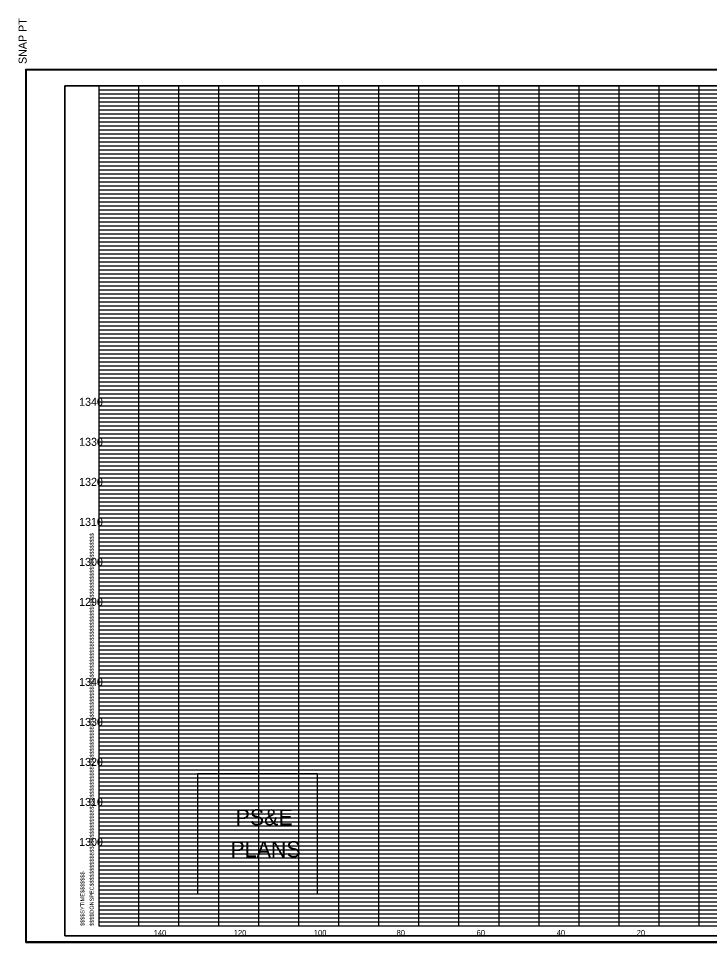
# Model space of a CAD drawing. Extents: x 980 to 1324, y 978 to 2847.
# Drawn here: x 979.9 to 1152.6, y 1805.9 to 2036.8 of the extents above; entities that cross this region are included whole.
import ezdxf

# ---------------------------------------------------------------- set-up
doc = ezdxf.new("R2010")
doc.units = 0
for name, color, linetype in [('DESIGN - SHEET - Corner Text', 7, 'Continuous'), ('DESIGN - SHEET - Light Grid', 7, 'Continuous'), ('DESIGN - SHEET - Linework', 7, 'Continuous'), ('DESIGN - SHEET - Plot Shape', 7, 'Continuous'), ('DESIGN - TYPICAL - Text', 7, 'Continuous')]:
    doc.layers.add(name, color=color, linetype=linetype)

# ---------------------------------------------------------------- blocks, each defined once
blk = doc.blocks.new('XSTSHT')
at = {"layer": 'DESIGN - SHEET - Light Grid'}
for p, q in [((0, 20.9), (8, 20.9)), ((0, 20.8), (8, 20.8)), ((8, 20.9), (16, 20.9)), ((8, 20.8), (16, 20.8)), ((0, 20.7), (8, 20.7)), ((0, 20.6), (8, 20.6)), ((8, 20.7), (16, 20.7)), ((8, 20.6), (16, 20.6)), ((0, 20.5), (8, 20.5)), ((0, 20.4), (8, 20.4)), ((8, 20.5), (16, 20.5)), ((8, 20.4), (16, 20.4)), ((0, 20.3), (8, 20.3)), ((0, 20.2), (8, 20.2)), ((0, 20.1), (8, 20.1)), ((8, 20.3), (16, 20.3)), ((8, 20.2), (16, 20.2)), ((8, 20.1), (16, 20.1)), ((0, 19.9), (8, 19.9)), ((8, 19.9), (16, 19.9)), ((0, 19.8), (8, 19.8)), ((0, 19.7), (8, 19.7)), ((8, 19.8), (16, 19.8)), ((8, 19.7), (16, 19.7)), ((0, 19.6), (8, 19.6)), ((0, 19.5), (8, 19.5)), ((0, 19.4), (8, 19.4)), ((8, 19.6), (16, 19.6)), ((8, 19.5), (16, 19.5)), ((8, 19.4), (16, 19.4)), ((0, 19.3), (8, 19.3)), ((0, 19.2), (8, 19.2)), ((8, 19.3), (16, 19.3)), ((8, 19.2), (16, 19.2)), ((0, 19.1), (8, 19.1)), ((8, 19.1), (16, 19.1)), ((0, 18.9), (8, 18.9)), ((0, 18.8), (8, 18.8)), ((8, 18.9), (16, 18.9)), ((8, 18.8), (16, 18.8)), ((0, 18.7), (8, 18.7)), ((0, 18.6), (8, 18.6)), ((0, 18.5), (8, 18.5)), ((8, 18.7), (16, 18.7)), ((8, 18.6), (16, 18.6)), ((8, 18.5), (16, 18.5)), ((0, 18.4), (8, 18.4)), ((0, 18.3), (8, 18.3)), ((8, 18.4), (16, 18.4)), ((8, 18.3), (16, 18.3)), ((0, 18.2), (8, 18.2)), ((0, 18.1), (8, 18.1)), ((8, 18.2), (16, 18.2)), ((8, 18.1), (16, 18.1)), ((0, 17.9), (8, 17.9)), ((0, 17.8), (8, 17.8)), ((8, 17.9), (16, 17.9)), ((8, 17.8), (16, 17.8)), ((0, 17.7), (8, 17.7)), ((0, 17.6), (8, 17.6)), ((8, 17.7), (16, 17.7)), ((8, 17.6), (16, 17.6)), ((0, 17.5), (8, 17.5)), ((0, 17.4), (8, 17.4)), ((8, 17.5), (16, 17.5)), ((8, 17.4), (16, 17.4)), ((0, 17.3), (8, 17.3)), ((0, 17.2), (8, 17.2)), ((0, 17.1), (8, 17.1)), ((8, 17.3), (16, 17.3)), ((8, 17.2), (16, 17.2)), ((8, 17.1), (16, 17.1)), ((0, 16.9), (8, 16.9)), ((8, 16.9), (16, 16.9)), ((0, 16.8), (8, 16.8)), ((0, 16.7), (8, 16.7)), ((8, 16.8), (16, 16.8)), ((8, 16.7), (16, 16.7)), ((0, 16.6), (8, 16.6)), ((0, 16.5), (8, 16.5)), ((0, 16.4), (8, 16.4)), ((8, 16.6), (16, 16.6)), ((8, 16.5), (16, 16.5)), ((8, 16.4), (16, 16.4)), ((0, 16.3), (8, 16.3)), ((0, 16.2), (8, 16.2)), ((8, 16.3), (16, 16.3)), ((8, 16.2), (16, 16.2)), ((0, 16.1), (8, 16.1)), ((8, 16.1), (16, 16.1)), ((0, 15.9), (8, 15.9)), ((0, 15.8), (8, 15.8)), ((8, 15.9), (16, 15.9)), ((8, 15.8), (16, 15.8)), ((0, 15.7), (8, 15.7)), ((0, 15.6), (8, 15.6)), ((0, 15.5), (8, 15.5)), ((8, 15.7), (16, 15.7)), ((8, 15.6), (16, 15.6)), ((8, 15.5), (16, 15.5)), ((0, 15.4), (8, 15.4)), ((0, 15.3), (8, 15.3)), ((8, 15.4), (16, 15.4)), ((8, 15.3), (16, 15.3)), ((0, 15.2), (8, 15.2)), ((0, 15.1), (8, 15.1)), ((8, 15.2), (16, 15.2)), ((8, 15.1), (16, 15.1)), ((0, 14.9), (8, 14.9)), ((0, 14.8), (8, 14.8)), ((8, 14.9), (16, 14.9)), ((8, 14.8), (16, 14.8)), ((0, 14.7), (8, 14.7)), ((0, 14.6), (8, 14.6)), ((8, 14.7), (16, 14.7)), ((8, 14.6), (16, 14.6)), ((0, 14.5), (8, 14.5)), ((0, 14.4), (8, 14.4)), ((8, 14.5), (16, 14.5)), ((8, 14.4), (16, 14.4)), ((0, 14.3), (8, 14.3)), ((0, 14.2), (8, 14.2)), ((0, 14.1), (8, 14.1)), ((8, 14.3), (16, 14.3)), ((8, 14.2), (16, 14.2)), ((8, 14.1), (16, 14.1)), ((0, 13.9), (8, 13.9)), ((8, 13.9), (16, 13.9)), ((0, 13.8), (8, 13.8)), ((0, 13.7), (8, 13.7)), ((8, 13.8), (16, 13.8)), ((8, 13.7), (16, 13.7)), ((0, 13.6), (8, 13.6)), ((0, 13.5), (8, 13.5)), ((0, 13.4), (8, 13.4)), ((8, 13.6), (16, 13.6)), ((8, 13.5), (16, 13.5)), ((8, 13.4), (16, 13.4)), ((0, 13.3), (8, 13.3)), ((0, 13.2), (8, 13.2)), ((8, 13.3), (16, 13.3)), ((8, 13.2), (16, 13.2)), ((0, 13.1), (8, 13.1)), ((8, 13.1), (16, 13.1)), ((0, 12.9), (8, 12.9)), ((0, 12.8), (8, 12.8)), ((8, 12.9), (16, 12.9)), ((8, 12.8), (16, 12.8)), ((0, 12.7), (8, 12.7)), ((0, 12.6), (8, 12.6)), ((0, 12.5), (8, 12.5)), ((8, 12.7), (16, 12.7)), ((8, 12.6), (16, 12.6)), ((8, 12.5), (16, 12.5)), ((0, 12.4), (8, 12.4)), ((0, 12.3), (8, 12.3)), ((8, 12.4), (16, 12.4)), ((8, 12.3), (16, 12.3)), ((0, 12.2), (8, 12.2)), ((0, 12.1), (8, 12.1)), ((8, 12.2), (16, 12.2)), ((8, 12.1), (16, 12.1)), ((0, 11.9), (8, 11.9)), ((0, 11.8), (8, 11.8)), ((8, 11.9), (16, 11.9)), ((8, 11.8), (16, 11.8)), ((0, 11.7), (8, 11.7)), ((0, 11.6), (8, 11.6)), ((8, 11.7), (16, 11.7)), ((8, 11.6), (16, 11.6)), ((0, 11.5), (8, 11.5)), ((0, 11.4), (8, 11.4)), ((8, 11.5), (16, 11.5)), ((8, 11.4), (16, 11.4)), ((0, 11.3), (8, 11.3)), ((0, 11.2), (8, 11.2)), ((0, 11.1), (8, 11.1)), ((8, 11.3), (16, 11.3)), ((8, 11.2), (16, 11.2)), ((8, 11.1), (16, 11.1)), ((0, 10.9), (8, 10.9)), ((8, 10.9), (16, 10.9)), ((0, 10.8), (8, 10.8)), ((0, 10.7), (8, 10.7)), ((8, 10.8), (16, 10.8)), ((8, 10.7), (16, 10.7)), ((0, 10.6), (8, 10.6)), ((0, 10.5), (8, 10.5)), ((0, 10.4), (8, 10.4)), ((8, 10.6), (16, 10.6)), ((8, 10.5), (16, 10.5)), ((8, 10.4), (16, 10.4)), ((0, 10.3), (8, 10.3)), ((0, 10.2), (8, 10.2)), ((8, 10.3), (16, 10.3)), ((8, 10.2), (16, 10.2)), ((0, 10.1), (8, 10.1)), ((8, 10.1), (16, 10.1)), ((0, 9.9), (8, 9.9)), ((0, 9.8), (8, 9.8)), ((0, 9.7), (8, 9.7)), ((8, 9.9), (16, 9.9)), ((8, 9.8), (16, 9.8)), ((8, 9.7), (16, 9.7)), ((0, 9.6), (8, 9.6)), ((0, 9.5), (8, 9.5)), ((8, 9.6), (16, 9.6)), ((8, 9.5), (16, 9.5)), ((0, 9.4), (8, 9.4)), ((0, 9.3), (8, 9.3)), ((8, 9.4), (16, 9.4)), ((8, 9.3), (16, 9.3)), ((0, 9.2), (8, 9.2)), ((0, 9.1), (8, 9.1)), ((8, 9.2), (16, 9.2)), ((8, 9.1), (16, 9.1)), ((0, 8.9), (8, 8.9)), ((0, 8.8), (8, 8.8)), ((8, 8.9), (16, 8.9)), ((8, 8.8), (16, 8.8)), ((0, 8.7), (8, 8.7)), ((0, 8.6), (8, 8.6)), ((8, 8.7), (16, 8.7)), ((8, 8.6), (16, 8.6)), ((0, 8.5), (8, 8.5)), ((0, 8.4), (8, 8.4)), ((8, 8.5), (16, 8.5)), ((8, 8.4), (16, 8.4)), ((0, 8.3), (8, 8.3)), ((0, 8.2), (8, 8.2)), ((0, 8.1), (8, 8.1)), ((8, 8.3), (16, 8.3)), ((8, 8.2), (16, 8.2)), ((8, 8.1), (16, 8.1)), ((0, 7.9), (8, 7.9)), ((8, 7.9), (16, 7.9)), ((0, 7.8), (8, 7.8)), ((0, 7.7), (8, 7.7)), ((8, 7.8), (16, 7.8)), ((8, 7.7), (16, 7.7)), ((0, 7.6), (8, 7.6)), ((0, 7.5), (8, 7.5)), ((0, 7.4), (8, 7.4)), ((8, 7.6), (16, 7.6)), ((8, 7.5), (16, 7.5)), ((8, 7.4), (16, 7.4)), ((0, 7.3), (8, 7.3)), ((0, 7.2), (8, 7.2)), ((8, 7.3), (16, 7.3)), ((8, 7.2), (16, 7.2)), ((0, 7.1), (8, 7.1)), ((8, 7.1), (16, 7.1)), ((0, 6.9), (8, 6.9)), ((0, 6.8), (8, 6.8)), ((0, 6.7), (8, 6.7)), ((8, 6.9), (16, 6.9)), ((8, 6.8), (16, 6.8)), ((8, 6.7), (16, 6.7)), ((0, 6.6), (8, 6.6)), ((0, 6.5), (8, 6.5)), ((8, 6.6), (16, 6.6)), ((8, 6.5), (16, 6.5)), ((0, 6.4), (8, 6.4)), ((0, 6.3), (8, 6.3)), ((8, 6.4), (16, 6.4)), ((8, 6.3), (16, 6.3)), ((0, 6.2), (8, 6.2)), ((0, 6.1), (8, 6.1)), ((8, 6.2), (16, 6.2)), ((8, 6.1), (16, 6.1)), ((0, 5.9), (8, 5.9)), ((0, 5.8), (8, 5.8)), ((8, 5.9), (16, 5.9)), ((8, 5.8), (16, 5.8)), ((0, 5.7), (8, 5.7)), ((0, 5.6), (8, 5.6)), ((8, 5.7), (16, 5.7)), ((8, 5.6), (16, 5.6)), ((0, 5.5), (8, 5.5)), ((0, 5.4), (8, 5.4)), ((8, 5.5), (16, 5.5)), ((8, 5.4), (16, 5.4)), ((0, 5.3), (8, 5.3)), ((0, 5.2), (8, 5.2)), ((0, 5.1), (8, 5.1)), ((8, 5.3), (16, 5.3)), ((8, 5.2), (16, 5.2)), ((8, 5.1), (16, 5.1)), ((0, 4.9), (8, 4.9)), ((8, 4.9), (16, 4.9)), ((0, 4.8), (8, 4.8)), ((0, 4.7), (8, 4.7)), ((8, 4.8), (16, 4.8)), ((8, 4.7), (16, 4.7)), ((0, 4.6), (8, 4.6)), ((0, 4.5), (8, 4.5)), ((0, 4.4), (8, 4.4)), ((8, 4.6), (16, 4.6)), ((8, 4.5), (16, 4.5)), ((8, 4.4), (16, 4.4)), ((0, 4.3), (8, 4.3)), ((0, 4.2), (8, 4.2)), ((8, 4.3), (16, 4.3)), ((8, 4.2), (16, 4.2)), ((0, 4.1), (8, 4.1)), ((8, 4.1), (16, 4.1)), ((0, 3.9), (8, 3.9)), ((0, 3.8), (8, 3.8)), ((0, 3.7), (8, 3.7)), ((8, 3.9), (16, 3.9)), ((8, 3.8), (16, 3.8)), ((8, 3.7), (16, 3.7)), ((0, 3.6), (8, 3.6)), ((0, 3.5), (8, 3.5)), ((8, 3.6), (16, 3.6)), ((8, 3.5), (16, 3.5)), ((0, 3.4), (8, 3.4)), ((0, 3.3), (8, 3.3)), ((8, 3.4), (16, 3.4)), ((8, 3.3), (16, 3.3)), ((0, 3.2), (8, 3.2)), ((0, 3.1), (8, 3.1)), ((8, 3.2), (16, 3.2)), ((8, 3.1), (16, 3.1)), ((0, 2.9), (8, 2.9)), ((0, 2.8), (8, 2.8)), ((8, 2.9), (16, 2.9)), ((8, 2.8), (16, 2.8)), ((0, 2.7), (8, 2.7)), ((0, 2.6), (8, 2.6)), ((8, 2.7), (16, 2.7)), ((8, 2.6), (16, 2.6)), ((0, 2.5), (8, 2.5)), ((0, 2.4), (8, 2.4)), ((8, 2.5), (16, 2.5)), ((8, 2.4), (16, 2.4)), ((0, 2.3), (8, 2.3)), ((0, 2.2), (8, 2.2)), ((0, 2.1), (8, 2.1)), ((8, 2.3), (16, 2.3)), ((8, 2.2), (16, 2.2)), ((8, 2.1), (16, 2.1)), ((0, 1.9), (8, 1.9)), ((8, 1.9), (16, 1.9)), ((0, 1.8), (8, 1.8)), ((0, 1.7), (8, 1.7)), ((8, 1.8), (16, 1.8)), ((8, 1.7), (16, 1.7)), ((0, 1.6), (8, 1.6)), ((0, 1.5), (8, 1.5)), ((0, 1.4), (8, 1.4)), ((8, 1.6), (16, 1.6)), ((8, 1.5), (16, 1.5)), ((8, 1.4), (16, 1.4)), ((0, 1.3), (8, 1.3)), ((0, 1.2), (8, 1.2)), ((8, 1.3), (16, 1.3)), ((8, 1.2), (16, 1.2)), ((0, 1.1), (8, 1.1)), ((8, 1.1), (16, 1.1)), ((0, 0.9), (8, 0.9)), ((0, 0.8), (8, 0.8)), ((0, 0.7), (8, 0.7)), ((8, 0.9), (16, 0.9)), ((8, 0.8), (16, 0.8)), ((8, 0.7), (16, 0.7)), ((0, 0.6), (8, 0.6)), ((0, 0.5), (8, 0.5)), ((8, 0.6), (16, 0.6)), ((8, 0.5), (16, 0.5)), ((0, 0.4), (8, 0.4)), ((0, 0.3), (8, 0.3)), ((8, 0.4), (16, 0.4)), ((8, 0.3), (16, 0.3)), ((0, 0.2), (8, 0.2)), ((0, 0.1), (8, 0.1)), ((8, 0.2), (16, 0.2)), ((8, 0.1), (16, 0.1))]:
    blk.add_line(p, q, dxfattribs=at)
at = {"layer": 'DESIGN - SHEET - Linework'}
for p, q in [((-1.823, -0.414), (-1.823, 21.414)), ((-1.823, 21.414), (32.217, 21.414)), ((1, 0), (1, 21)), ((2, 0), (2, 21)), ((3, 0), (3, 21)), ((4, 0), (4, 21)), ((5, 0), (5, 21)), ((6, 0), (6, 21)), ((7, 0), (7, 21)), ((8, 0), (8, 21)), ((9, 0), (9, 21)), ((10, 0), (10, 21)), ((11, 0), (11, 21)), ((12, 0), (12, 21)), ((13, 0), (13, 21)), ((14, 0), (14, 21)), ((15, 0), (15, 21)), ((0, 20), (28, 20)), ((0, 19), (32, 19)), ((0, 18), (32, 18)), ((0, 17), (32, 17)), ((0, 16), (32, 16)), ((0, 15), (32, 15)), ((0, 14), (32, 14)), ((0, 13), (32, 13)), ((0, 12), (32, 12)), ((0, 11), (32, 11)), ((0, 10), (32, 10)), ((0, 9), (32, 9)), ((0, 8), (32, 8)), ((0, 7), (32, 7)), ((0, 6), (32, 6)), ((0, 5), (32, 5)), ((0, 4), (32, 4)), ((0, 3), (32, 3)), ((0, 2), (32, 2)), ((0, 1), (32, 1)), ((-1.823, -0.414), (32.217, -0.414))]:
    blk.add_line(p, q, dxfattribs=at)
blk.add_lwpolyline([(0, 21), (0, 0), (32, 0), (32, 21), (0, 21)], dxfattribs=at)
at = {"layer": 'DESIGN - SHEET - Plot Shape'}
for points in [[(-1.803, 21.394), (32.197, 21.394), (32.197, -0.394), (-1.803, -0.394)], [(-0.85, 21), (32, 21), (32, -0.25), (-0.85, -0.25)]]:
    blk.add_lwpolyline(points, close=True, dxfattribs=at)
at = {"layer": 'DESIGN - SHEET - Corner Text'}
for s, height, p in [('  SNAP PT', 0.2, (-1.803, 21.394)), ('$$$$DGNSPEC$$$$$$$$$$$$$$$$$$$$$$$$$$$$$$$$$$$$$$$$$$$$$$$$$$$$$$$$$$$$$$$$$$$$$$$$$$$$$$$$$$$$$$$$$$$$$$$$$$$$$$$$$$$$$$$$$$$', 0.100002, (-0.126, 0)), ('$$$$SYTIME$$$$$$$', 0.1, (-0.358, 0))]:
    blk.add_text(s, height=height, rotation=90, dxfattribs=at).set_placement(p)

msp = doc.modelspace()

# ---------------------------------------------------------------- linework, layer by layer
at = {"layer": 'DESIGN - SHEET - Corner Text'}
msp.add_lwpolyline([(1024.66, 1848), (1024.66, 1818), (1054.66, 1818), (1054.66, 1848)], close=True, dxfattribs=at)
at = {"layer": 'DESIGN - SHEET - Plot Shape'}
msp.add_lwpolyline([(991.5, 1807.5), (1320, 1807.5), (1320, 2020), (991.5, 2020)], close=True, dxfattribs=at)

# ---------------------------------------------------------------- block references
at = {"layer": 'DESIGN - SHEET - Plot Shape', "xscale": 10, "yscale": 10}
msp.add_blockref('XSTSHT', (1000, 1810), dxfattribs=at)

# ---------------------------------------------------------------- texts
at = {"layer": 'DESIGN - SHEET - Corner Text'}
for s, p in [('PS&E', (1034.18, 1835.18)), ('PLANS', (1032.89, 1827.18))]:
    msp.add_text(s, height=4, dxfattribs=at).set_placement(p)
at = {"layer": 'DESIGN - TYPICAL - Text'}
for s, height, p in [('     1340     ', 2, (991.37, 1940)), ('     1330     ', 2, (991.37, 1930)), ('     1320     ', 2, (991.37, 1920)), ('     1310     ', 2, (991.37, 1910)), ('     1300     ', 2, (991.37, 1900)), ('     1290     ', 2, (991.37, 1890)), ('     1340     ', 2, (991.37, 1870)), ('     1330     ', 2, (991.37, 1860)), ('     1320     ', 2, (991.37, 1850)), ('     1310     ', 2, (991.37, 1840)), ('     1300     ', 2, (991.37, 1830)), ('     140     ', 1.4, (1011.14, 1807.6)), ('     120     ', 1.4, (1031.14, 1807.6)), ('     100     ', 1.4, (1051.14, 1807.6)), ('     80     ', 1.4, (1071.82, 1807.6)), ('     60     ', 1.4, (1091.82, 1807.6)), ('     40     ', 1.4, (1111.82, 1807.6)), ('     20     ', 1.4, (1131.82, 1807.6))]:
    msp.add_text(s, height=height, dxfattribs=at).set_placement(p)

doc.saveas('drawing.dxf')
